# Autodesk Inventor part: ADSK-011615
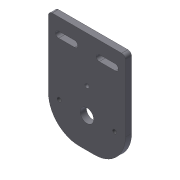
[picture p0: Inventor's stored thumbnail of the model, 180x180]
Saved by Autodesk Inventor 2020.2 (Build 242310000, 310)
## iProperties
Created: 2000-02
Part Number: ADSK-011615
Material: Pearson HRS
Document SubType Name: Modeling
Description: PLT-24,FH,BX,04,050,065,NNDD,BEARING MOUNT PLATE
Designer: sspink
Density: 7.83 g/cm^3
Appearance: Métal - Acier
Mass: 1438.7 g
Surface Area: 450.567 cm^2
Volume: 183.742 cm^3
Control State: 0
Checked Out: False
Master: False
Shininess: 0.0
Length Units: 11269
Angle Units: 11279
Time Units: 11290
Mass Units: 11283
Length Display Precision: 3
Angle Display Precision: 2
Compacted: True
Cutlength: 6.5
Material Desc: FLAT,HRS,0.375X05.000
Material_Number: A084412
Dimensions: 165x10x125 mm
Mass: 1,439 kg
VLT_Material: Pearson HRS
Density: 0.0
Volumn: 0.0
Area: 0.0
PropertySet Name: Model Information
Author: sspink
Revision Number: -
Title: PLT-24,FH,BX,04,050,065,NNDD,BEARING MOUNT PLATE
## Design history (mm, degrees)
node "Solide1"
  node "Extrusion1" dims "d2" = 10, "d3" = 0
  node "Hole1" dims "d5" = 22, "d6" = 9.525, "d7" = 6.35, "d8" = 60 deg, "d9" = 19.05, "d10" = 118 deg, "d38" = 6
  node "Fillet1" dims "d11" = 50
  node "Extrusion2" dims "d17" = 9.525, "d18" = 0
  node "Fillet2" dims "d19" = 6
  node "Hole2" dims "d22" = 6.74688, "d23" = 9.525, "d24" = 6.35, "d25" = 60 deg, "d26" = 19.05, "d27" = 118 deg
  node "Hole3" dims "d32" = 6.647, "d33" = 9.525, "d34" = 6.35, "d35" = 60 deg, "d36" = 19.05, "d37" = 118 deg, "d44" = 16
sketch "Sketch1"
  geometry: L1 (-62.5, -82.5)-(62.5, -82.5); L2 (62.5, -82.5)-(62.5, 82.5); L3 (62.5, 82.5)-(-62.5, 82.5); L4 (-62.5, 82.5)-(-62.5, -82.5); 3 further points
  constraints: 8 end point, 2 midpoint, 2 parallel, 1 horizontal, 1 horizontal alignment, 1 perpendicular, 1 vertical alignment
  dimensions: "d0" = 125 distance between parallel lines of L2 L4; "d1" = 165 distance between parallel lines of L1 L3
sketch "Sketch2"
  geometry: L1 (62.5, -82.5)-(-62.5, -82.5) reference; L2 (-62.5, 82.5)-(62.5, 82.5) reference; L3 (0, 82.5)-(0, -82.5); 1 further point
  constraints: 2 end point, 2 midpoint, 1 point on line
  dimensions: "d4" = 49 distance from line of point (0, -33.5) L1
sketch "Sketch3"
  geometry: L1 (-62.5, 82.5)-(62.5, 82.5) reference; L2 (-46, 62.5)-(-20, 62.5); L3 (-20, 62.5)-(-20, 52.5); L4 (-20, 52.5)-(-46, 52.5); L5 (-46, 52.5)-(-46, 62.5); L6 (20, 62.5)-(46, 62.5); L7 (46, 62.5)-(46, 52.5); L8 (46, 52.5)-(20, 52.5); L9 (20, 52.5)-(20, 62.5); L10 (-20, 57.5)-(20, 57.5); A1 r 5 centre (-46, 57.5) between (-46, 62.5) and (-46, 52.5); A2 r 5 centre (-20, 57.5) between (-20, 52.5) and (-20, 62.5); A3 r 5 centre (20, 57.5) between (20, 62.5) and (20, 52.5); A4 r 5 centre (46, 57.5) between (46, 52.5) and (46, 62.5); 2 further points
  constraints: 18 end point, 8 point on circle, 4 centre point, 4 parallel, 4 tangent, 3 horizontal, 2 midpoint, 2 perpendicular, 1 collinear, 1 equal radius, 1 horizontal alignment, 1 vertical alignment
  dimensions: "d13" = 10 distance between parallel lines of L4 L2; "d15" = 25 distance from line of A1.centre L1; "d39" = 26 distance of L6.start L6.end; "d40" = 26 distance of L2.start L2.end (derived); "d41" = 40 distance of L10.start L10.end
sketch "Sketch4"
  geometry: L1 (-56.5, 82.5)-(56.5, 82.5) reference; C1 r 11 at (0, -33.5) reference; 2 further points
  constraints: 1 midpoint, 1 vertical alignment
  dimensions: "d42" = 42 distance of point (0, 8.5) C1.centre
sketch "Sketch5"
  geometry: L1 (-56.5, 82.5)-(56.5, 82.5) reference; L2 (12.5, -82.5)-(-12.5, -82.5) reference; L3 (0, 82.5)-(0, -82.5); L4 (-45, -33.5)-(45, -33.5); C1 r 11 at (0, -33.5) reference; 1 further point
  constraints: 4 end point, 3 midpoint, 1 coincident, 1 horizontal, 1 point on line
  dimensions: "d43" = 90 distance of L4.start L4.end
node "Corps solides"
node "Corps surfaciques"
